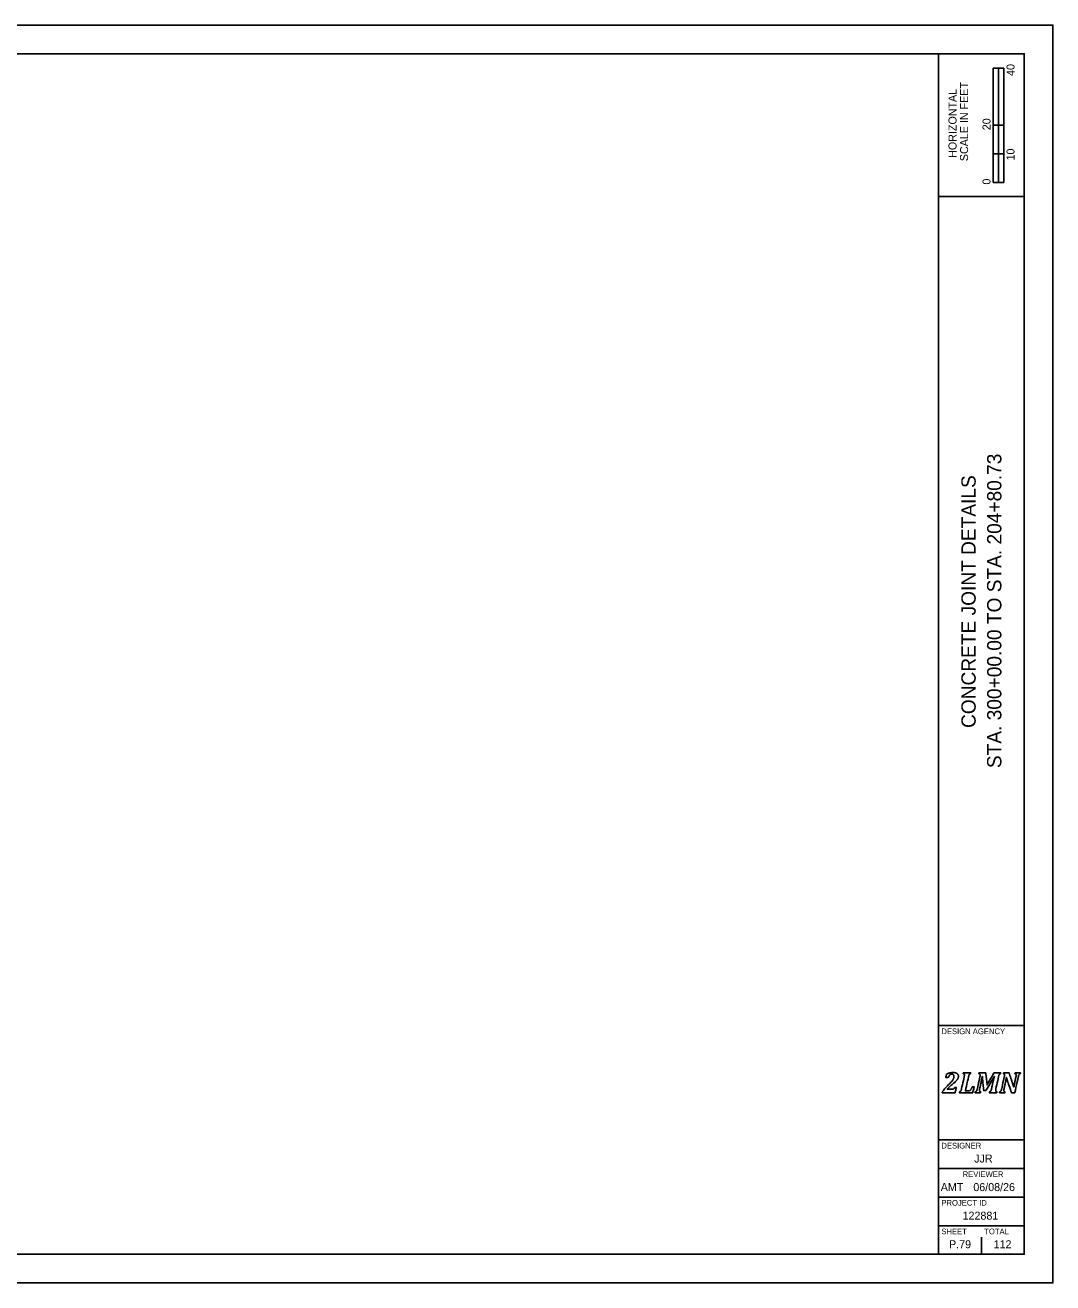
# Model space of a CAD drawing. Extents: x -2 to 34, y 0 to 22.
# Drawn here: x 16.02 to 34, y 0 to 22 of the extents above; entities that cross this region are included whole.
import ezdxf

# ---------------------------------------------------------------- set-up
doc = ezdxf.new("R2010")
doc.units = 0
for name, color, linetype in [('SH_Border', 7, 'Continuous'), ('SH_Cut_Line', 7, 'Continuous'), ('SH_Data', 7, 'Continuous')]:
    doc.layers.add(name, color=color, linetype=linetype)

msp = doc.modelspace()

# ---------------------------------------------------------------- linework, layer by layer
at = {"layer": 'SH_Border'}
for p, q in [((32, 0.5), (32, 21.5)), ((32, 19), (33.5, 19)), ((32, 4.5), (33.5, 4.5)), ((32, 2.5), (33.5, 2.5)), ((32, 2), (33.5, 2)), ((32, 1.5), (33.5, 1.5)), ((32, 1), (33.5, 1))]:
    msp.add_line(p, q, dxfattribs=at)
msp.add_lwpolyline([(1.5, 21.5), (33.5, 21.5), (33.5, 0.5), (1.5, 0.5)], close=True, dxfattribs=at)
at = {"layer": 'SH_Cut_Line'}
msp.add_lwpolyline([(0, 0), (34, 0), (34, 22), (0, 22)], close=True, dxfattribs=at)
at = {"layer": 'SH_Data'}
for p, q in [((32.957, 19.25), (32.957, 21.25)), ((33.144, 21.25), (32.957, 21.25)), ((32.957, 20.25), (32.957, 21.25)), ((32.957, 21.25), (33.05, 21.25)), ((33.05, 21.25), (33.051, 21.25)), ((33.051, 21.25), (33.051, 20.25)), ((33.144, 21.25), (33.144, 19.25)), ((33.051, 20.25), (32.957, 20.25)), ((33.143, 20.25), (33.05, 20.25)), ((33.05, 20.25), (33.05, 19.75)), ((33.143, 19.75), (33.143, 20.25)), ((33.05, 19.75), (32.957, 19.75)), ((32.957, 19.75), (32.957, 19.25)), ((33.05, 19.25), (33.05, 19.75)), ((33.05, 19.75), (33.143, 19.75)), ((33.144, 19.25), (32.957, 19.25)), ((32.957, 19.25), (33.05, 19.25)), ((32.75, 3.5), (32.75, 3.5)), ((32.375, 0.675), (32.375, 0.675)), ((32.75, 0.5), (32.75, 0.8))]:
    msp.add_line(p, q, dxfattribs=at)
for points in [[(32.237, 3.388), (32.246, 3.388), (32.253, 3.389), (32.258, 3.39), (32.263, 3.392), (32.267, 3.394), (32.27, 3.397), (32.273, 3.401), (32.277, 3.408), (32.281, 3.417), (32.281, 3.417), (32.312, 3.417), (32.312, 3.417), (32.312, 3.417), (32.29, 3.326), (32.29, 3.326), (32.29, 3.326), (32.066, 3.326), (32.066, 3.326), (32.066, 3.326), (32.069, 3.343), (32.069, 3.343), (32.078, 3.358), (32.091, 3.375), (32.106, 3.394), (32.122, 3.412), (32.144, 3.435), (32.172, 3.462), (32.197, 3.486), (32.217, 3.506), (32.23, 3.521), (32.243, 3.537), (32.253, 3.551), (32.259, 3.566), (32.266, 3.58), (32.269, 3.595), (32.269, 3.61), (32.269, 3.622), (32.266, 3.632), (32.26, 3.64), (32.253, 3.647), (32.245, 3.65), (32.234, 3.65), (32.22, 3.65), (32.208, 3.646), (32.198, 3.636), (32.188, 3.627), (32.18, 3.613), (32.172, 3.593), (32.172, 3.593), (32.126, 3.593), (32.126, 3.593), (32.126, 3.593), (32.14, 3.654), (32.14, 3.654), (32.166, 3.663), (32.188, 3.669), (32.205, 3.673), (32.223, 3.676), (32.24, 3.678), (32.258, 3.678), (32.278, 3.678), (32.295, 3.675), (32.309, 3.669), (32.322, 3.664), (32.332, 3.656), (32.339, 3.646), (32.345, 3.637), (32.348, 3.626), (32.348, 3.613), (32.348, 3.602), (32.346, 3.591), (32.342, 3.581), (32.339, 3.571), (32.333, 3.56), (32.324, 3.549), (32.315, 3.539), (32.304, 3.526), (32.289, 3.513), (32.275, 3.499), (32.254, 3.482), (32.228, 3.46), (32.216, 3.45), (32.202, 3.438), (32.188, 3.425), (32.174, 3.412), (32.162, 3.4), (32.154, 3.391), (32.154, 3.391), (32.153, 3.388), (32.153, 3.388), (32.153, 3.388), (32.237, 3.388), (32.237, 3.388)], [(32.237, 3.388), (32.237, 3.388), (32.153, 3.388), (32.153, 3.388), (32.153, 3.388), (32.154, 3.391), (32.154, 3.391), (32.162, 3.4), (32.174, 3.412), (32.188, 3.425), (32.202, 3.438), (32.216, 3.45), (32.228, 3.46), (32.254, 3.482), (32.275, 3.499), (32.289, 3.513), (32.304, 3.526), (32.315, 3.539), (32.324, 3.549), (32.333, 3.56), (32.339, 3.571), (32.342, 3.581), (32.346, 3.591), (32.348, 3.602), (32.348, 3.613), (32.348, 3.626), (32.345, 3.637), (32.339, 3.646), (32.332, 3.656), (32.322, 3.664), (32.309, 3.669), (32.295, 3.675), (32.278, 3.678), (32.258, 3.678), (32.24, 3.678), (32.223, 3.676), (32.205, 3.673), (32.188, 3.669), (32.166, 3.663), (32.14, 3.654), (32.14, 3.654), (32.126, 3.593), (32.126, 3.593), (32.126, 3.593), (32.172, 3.593), (32.172, 3.593), (32.18, 3.613), (32.188, 3.627), (32.198, 3.636), (32.208, 3.646), (32.22, 3.65), (32.234, 3.65), (32.245, 3.65), (32.253, 3.647), (32.26, 3.64), (32.266, 3.632), (32.269, 3.622), (32.269, 3.61), (32.269, 3.595), (32.266, 3.58), (32.259, 3.566), (32.253, 3.551), (32.243, 3.537), (32.23, 3.521), (32.217, 3.506), (32.197, 3.486), (32.172, 3.462), (32.144, 3.435), (32.122, 3.412), (32.106, 3.394), (32.091, 3.375), (32.078, 3.358), (32.069, 3.343), (32.069, 3.343), (32.066, 3.326), (32.066, 3.326), (32.066, 3.326), (32.29, 3.326), (32.29, 3.326), (32.29, 3.326), (32.312, 3.417), (32.312, 3.417), (32.312, 3.417), (32.281, 3.417), (32.281, 3.417), (32.277, 3.408), (32.273, 3.401), (32.27, 3.397), (32.267, 3.394), (32.263, 3.392), (32.258, 3.39), (32.253, 3.389), (32.246, 3.388), (32.237, 3.388)], [(32.518, 3.356), (32.527, 3.356), (32.533, 3.357), (32.538, 3.358), (32.542, 3.36), (32.546, 3.362), (32.55, 3.365), (32.554, 3.368), (32.558, 3.372), (32.562, 3.377), (32.567, 3.382), (32.571, 3.388), (32.576, 3.397), (32.58, 3.405), (32.585, 3.415), (32.589, 3.427), (32.589, 3.427), (32.624, 3.427), (32.624, 3.427), (32.624, 3.427), (32.598, 3.326), (32.598, 3.326), (32.598, 3.326), (32.365, 3.326), (32.365, 3.326), (32.365, 3.326), (32.369, 3.343), (32.369, 3.343), (32.376, 3.345), (32.381, 3.348), (32.385, 3.351), (32.389, 3.355), (32.392, 3.36), (32.395, 3.366), (32.398, 3.373), (32.4, 3.382), (32.403, 3.395), (32.403, 3.395), (32.449, 3.605), (32.449, 3.605), (32.452, 3.615), (32.453, 3.625), (32.453, 3.635), (32.453, 3.642), (32.451, 3.647), (32.448, 3.651), (32.444, 3.654), (32.439, 3.656), (32.432, 3.657), (32.432, 3.657), (32.435, 3.674), (32.435, 3.674), (32.435, 3.674), (32.563, 3.674), (32.563, 3.674), (32.563, 3.674), (32.559, 3.657), (32.559, 3.657), (32.552, 3.655), (32.547, 3.652), (32.543, 3.649), (32.539, 3.645), (32.536, 3.64), (32.533, 3.634), (32.531, 3.627), (32.528, 3.618), (32.525, 3.605), (32.525, 3.605), (32.47, 3.356), (32.47, 3.356), (32.47, 3.356), (32.518, 3.356), (32.518, 3.356)], [(32.518, 3.356), (32.518, 3.356), (32.47, 3.356), (32.47, 3.356), (32.47, 3.356), (32.525, 3.605), (32.525, 3.605), (32.528, 3.618), (32.531, 3.627), (32.533, 3.634), (32.536, 3.64), (32.539, 3.645), (32.543, 3.649), (32.547, 3.652), (32.552, 3.655), (32.559, 3.657), (32.559, 3.657), (32.563, 3.674), (32.563, 3.674), (32.563, 3.674), (32.435, 3.674), (32.435, 3.674), (32.435, 3.674), (32.432, 3.657), (32.432, 3.657), (32.439, 3.656), (32.444, 3.654), (32.448, 3.651), (32.451, 3.647), (32.453, 3.642), (32.453, 3.635), (32.453, 3.625), (32.452, 3.615), (32.449, 3.605), (32.449, 3.605), (32.403, 3.395), (32.403, 3.395), (32.4, 3.382), (32.398, 3.373), (32.395, 3.366), (32.392, 3.36), (32.389, 3.355), (32.385, 3.351), (32.381, 3.348), (32.376, 3.345), (32.369, 3.343), (32.369, 3.343), (32.365, 3.326), (32.365, 3.326), (32.365, 3.326), (32.598, 3.326), (32.598, 3.326), (32.598, 3.326), (32.624, 3.427), (32.624, 3.427), (32.624, 3.427), (32.589, 3.427), (32.589, 3.427), (32.585, 3.415), (32.58, 3.405), (32.576, 3.397), (32.571, 3.388), (32.567, 3.382), (32.562, 3.377), (32.558, 3.372), (32.554, 3.368), (32.55, 3.365), (32.546, 3.362), (32.542, 3.36), (32.538, 3.358), (32.533, 3.357), (32.527, 3.356), (32.518, 3.356)], [(32.829, 3.674), (32.829, 3.674), (32.849, 3.461), (32.849, 3.461), (32.849, 3.461), (32.969, 3.674), (32.969, 3.674), (32.969, 3.674), (33.087, 3.674), (33.087, 3.674), (33.087, 3.674), (33.084, 3.657), (33.084, 3.657), (33.077, 3.655), (33.071, 3.652), (33.067, 3.649), (33.064, 3.645), (33.06, 3.64), (33.058, 3.634), (33.055, 3.627), (33.052, 3.618), (33.05, 3.605), (33.05, 3.605), (33.003, 3.395), (33.003, 3.395), (33.002, 3.39), (33.002, 3.387), (33.001, 3.384), (33.001, 3.382), (33.001, 3.379), (33, 3.376), (33, 3.373), (33, 3.369), (33, 3.365), (33, 3.358), (33.002, 3.353), (33.005, 3.349), (33.008, 3.346), (33.014, 3.344), (33.021, 3.343), (33.021, 3.343), (33.018, 3.326), (33.018, 3.326), (33.018, 3.326), (32.89, 3.326), (32.89, 3.326), (32.89, 3.326), (32.893, 3.343), (32.893, 3.343), (32.9, 3.345), (32.906, 3.348), (32.91, 3.351), (32.914, 3.355), (32.917, 3.36), (32.919, 3.366), (32.922, 3.373), (32.925, 3.382), (32.928, 3.395), (32.928, 3.395), (32.951, 3.502), (32.951, 3.502), (32.954, 3.513), (32.957, 3.529), (32.962, 3.548), (32.967, 3.568), (32.972, 3.588), (32.978, 3.609), (32.978, 3.609), (32.973, 3.609), (32.973, 3.609), (32.965, 3.594), (32.957, 3.579), (32.948, 3.563), (32.948, 3.563), (32.833, 3.364), (32.833, 3.364), (32.833, 3.364), (32.792, 3.364), (32.792, 3.364), (32.792, 3.364), (32.775, 3.518), (32.775, 3.518), (32.773, 3.537), (32.772, 3.554), (32.77, 3.569), (32.769, 3.583), (32.768, 3.597), (32.768, 3.611), (32.768, 3.611), (32.764, 3.611), (32.764, 3.611), (32.761, 3.596), (32.758, 3.578), (32.755, 3.558), (32.751, 3.538), (32.747, 3.521), (32.744, 3.507), (32.744, 3.507), (32.72, 3.395), (32.72, 3.395), (32.719, 3.39), (32.718, 3.387), (32.718, 3.384), (32.717, 3.382), (32.717, 3.379), (32.717, 3.376), (32.717, 3.373), (32.716, 3.369), (32.716, 3.365), (32.716, 3.358), (32.718, 3.353), (32.721, 3.349), (32.725, 3.346), (32.73, 3.344), (32.738, 3.343), (32.738, 3.343), (32.734, 3.326), (32.734, 3.326), (32.734, 3.326), (32.641, 3.326), (32.641, 3.326), (32.641, 3.326), (32.644, 3.343), (32.644, 3.343), (32.651, 3.345), (32.657, 3.348), (32.661, 3.351), (32.665, 3.355), (32.668, 3.36), (32.67, 3.366), (32.673, 3.373), (32.676, 3.382), (32.679, 3.395), (32.679, 3.395), (32.725, 3.605), (32.725, 3.605), (32.727, 3.615), (32.728, 3.625), (32.728, 3.635), (32.728, 3.642), (32.727, 3.647), (32.723, 3.651), (32.72, 3.654), (32.715, 3.656), (32.707, 3.657), (32.707, 3.657), (32.711, 3.674), (32.711, 3.674), (32.711, 3.674), (32.829, 3.674), (32.829, 3.674)], [(32.829, 3.674), (32.829, 3.674), (32.711, 3.674), (32.711, 3.674), (32.711, 3.674), (32.707, 3.657), (32.707, 3.657), (32.715, 3.656), (32.72, 3.654), (32.723, 3.651), (32.727, 3.647), (32.728, 3.642), (32.728, 3.635), (32.728, 3.625), (32.727, 3.615), (32.725, 3.605), (32.725, 3.605), (32.679, 3.395), (32.679, 3.395), (32.676, 3.382), (32.673, 3.373), (32.67, 3.366), (32.668, 3.36), (32.665, 3.355), (32.661, 3.351), (32.657, 3.348), (32.651, 3.345), (32.644, 3.343), (32.644, 3.343), (32.641, 3.326), (32.641, 3.326), (32.641, 3.326), (32.734, 3.326), (32.734, 3.326), (32.734, 3.326), (32.738, 3.343), (32.738, 3.343), (32.73, 3.344), (32.725, 3.346), (32.721, 3.349), (32.718, 3.353), (32.716, 3.358), (32.716, 3.365), (32.716, 3.369), (32.717, 3.373), (32.717, 3.376), (32.717, 3.379), (32.717, 3.382), (32.718, 3.384), (32.718, 3.387), (32.719, 3.39), (32.72, 3.395), (32.72, 3.395), (32.744, 3.507), (32.744, 3.507), (32.747, 3.521), (32.751, 3.538), (32.755, 3.558), (32.758, 3.578), (32.761, 3.596), (32.764, 3.611), (32.764, 3.611), (32.768, 3.611), (32.768, 3.611), (32.768, 3.597), (32.769, 3.583), (32.77, 3.569), (32.772, 3.554), (32.773, 3.537), (32.775, 3.518), (32.775, 3.518), (32.792, 3.364), (32.792, 3.364), (32.792, 3.364), (32.833, 3.364), (32.833, 3.364), (32.833, 3.364), (32.948, 3.563), (32.948, 3.563), (32.957, 3.579), (32.965, 3.594), (32.973, 3.609), (32.973, 3.609), (32.978, 3.609), (32.978, 3.609), (32.972, 3.588), (32.967, 3.568), (32.962, 3.548), (32.957, 3.529), (32.954, 3.513), (32.951, 3.502), (32.951, 3.502), (32.928, 3.395), (32.928, 3.395), (32.925, 3.382), (32.922, 3.373), (32.919, 3.366), (32.917, 3.36), (32.914, 3.355), (32.91, 3.351), (32.906, 3.348), (32.9, 3.345), (32.893, 3.343), (32.893, 3.343), (32.89, 3.326), (32.89, 3.326), (32.89, 3.326), (33.018, 3.326), (33.018, 3.326), (33.018, 3.326), (33.021, 3.343), (33.021, 3.343), (33.014, 3.344), (33.008, 3.346), (33.005, 3.349), (33.002, 3.353), (33, 3.358), (33, 3.365), (33, 3.369), (33, 3.373), (33, 3.376), (33.001, 3.379), (33.001, 3.382), (33.001, 3.384), (33.002, 3.387), (33.002, 3.39), (33.003, 3.395), (33.003, 3.395), (33.05, 3.605), (33.05, 3.605), (33.052, 3.618), (33.055, 3.627), (33.058, 3.634), (33.06, 3.64), (33.064, 3.645), (33.067, 3.649), (33.071, 3.652), (33.077, 3.655), (33.084, 3.657), (33.084, 3.657), (33.087, 3.674), (33.087, 3.674), (33.087, 3.674), (32.969, 3.674), (32.969, 3.674), (32.969, 3.674), (32.849, 3.461), (32.849, 3.461), (32.849, 3.461), (32.829, 3.674), (32.829, 3.674)], [(33.137, 3.674), (33.137, 3.674), (33.234, 3.674), (33.234, 3.674), (33.234, 3.674), (33.283, 3.53), (33.283, 3.53), (33.296, 3.49), (33.307, 3.456), (33.315, 3.426), (33.315, 3.426), (33.318, 3.426), (33.318, 3.426), (33.323, 3.455), (33.329, 3.488), (33.337, 3.523), (33.337, 3.523), (33.355, 3.605), (33.355, 3.605), (33.357, 3.615), (33.358, 3.625), (33.358, 3.635), (33.358, 3.642), (33.357, 3.647), (33.353, 3.651), (33.35, 3.654), (33.345, 3.656), (33.337, 3.657), (33.337, 3.657), (33.341, 3.674), (33.341, 3.674), (33.341, 3.674), (33.434, 3.674), (33.434, 3.674), (33.434, 3.674), (33.431, 3.657), (33.431, 3.657), (33.424, 3.655), (33.418, 3.652), (33.414, 3.649), (33.41, 3.645), (33.407, 3.64), (33.405, 3.634), (33.402, 3.627), (33.399, 3.618), (33.396, 3.605), (33.396, 3.605), (33.335, 3.326), (33.335, 3.326), (33.335, 3.326), (33.277, 3.326), (33.277, 3.326), (33.277, 3.326), (33.216, 3.504), (33.216, 3.504), (33.211, 3.518), (33.207, 3.531), (33.204, 3.543), (33.2, 3.556), (33.195, 3.571), (33.19, 3.59), (33.19, 3.59), (33.186, 3.59), (33.186, 3.59), (33.185, 3.579), (33.182, 3.563), (33.179, 3.543), (33.175, 3.523), (33.17, 3.501), (33.165, 3.478), (33.165, 3.478), (33.147, 3.395), (33.147, 3.395), (33.146, 3.39), (33.145, 3.387), (33.145, 3.384), (33.144, 3.382), (33.144, 3.379), (33.144, 3.376), (33.143, 3.373), (33.143, 3.369), (33.143, 3.365), (33.143, 3.358), (33.145, 3.353), (33.148, 3.349), (33.152, 3.346), (33.157, 3.344), (33.164, 3.343), (33.164, 3.343), (33.161, 3.326), (33.161, 3.326), (33.161, 3.326), (33.067, 3.326), (33.067, 3.326), (33.067, 3.326), (33.071, 3.343), (33.071, 3.343), (33.078, 3.345), (33.083, 3.348), (33.087, 3.351), (33.091, 3.355), (33.094, 3.36), (33.097, 3.366), (33.1, 3.373), (33.102, 3.382), (33.105, 3.395), (33.105, 3.395), (33.151, 3.605), (33.151, 3.605), (33.154, 3.615), (33.155, 3.625), (33.155, 3.635), (33.155, 3.642), (33.153, 3.647), (33.15, 3.651), (33.146, 3.654), (33.141, 3.656), (33.134, 3.657), (33.134, 3.657), (33.137, 3.674), (33.137, 3.674)], [(33.137, 3.674), (33.137, 3.674), (33.134, 3.657), (33.134, 3.657), (33.141, 3.656), (33.146, 3.654), (33.15, 3.651), (33.153, 3.647), (33.155, 3.642), (33.155, 3.635), (33.155, 3.625), (33.154, 3.615), (33.151, 3.605), (33.151, 3.605), (33.105, 3.395), (33.105, 3.395), (33.102, 3.382), (33.1, 3.373), (33.097, 3.366), (33.094, 3.36), (33.091, 3.355), (33.087, 3.351), (33.083, 3.348), (33.078, 3.345), (33.071, 3.343), (33.071, 3.343), (33.067, 3.326), (33.067, 3.326), (33.067, 3.326), (33.161, 3.326), (33.161, 3.326), (33.161, 3.326), (33.164, 3.343), (33.164, 3.343), (33.157, 3.344), (33.152, 3.346), (33.148, 3.349), (33.145, 3.353), (33.143, 3.358), (33.143, 3.365), (33.143, 3.369), (33.143, 3.373), (33.144, 3.376), (33.144, 3.379), (33.144, 3.382), (33.145, 3.384), (33.145, 3.387), (33.146, 3.39), (33.147, 3.395), (33.147, 3.395), (33.165, 3.478), (33.165, 3.478), (33.17, 3.501), (33.175, 3.523), (33.179, 3.543), (33.182, 3.563), (33.185, 3.579), (33.186, 3.59), (33.186, 3.59), (33.19, 3.59), (33.19, 3.59), (33.195, 3.571), (33.2, 3.556), (33.204, 3.543), (33.207, 3.531), (33.211, 3.518), (33.216, 3.504), (33.216, 3.504), (33.277, 3.326), (33.277, 3.326), (33.277, 3.326), (33.335, 3.326), (33.335, 3.326), (33.335, 3.326), (33.396, 3.605), (33.396, 3.605), (33.399, 3.618), (33.402, 3.627), (33.405, 3.634), (33.407, 3.64), (33.41, 3.645), (33.414, 3.649), (33.418, 3.652), (33.424, 3.655), (33.431, 3.657), (33.431, 3.657), (33.434, 3.674), (33.434, 3.674), (33.434, 3.674), (33.341, 3.674), (33.341, 3.674), (33.341, 3.674), (33.337, 3.657), (33.337, 3.657), (33.345, 3.656), (33.35, 3.654), (33.353, 3.651), (33.357, 3.647), (33.358, 3.642), (33.358, 3.635), (33.358, 3.625), (33.357, 3.615), (33.355, 3.605), (33.355, 3.605), (33.337, 3.523), (33.337, 3.523), (33.329, 3.488), (33.323, 3.455), (33.318, 3.426), (33.318, 3.426), (33.315, 3.426), (33.315, 3.426), (33.307, 3.456), (33.296, 3.49), (33.283, 3.53), (33.283, 3.53), (33.234, 3.674), (33.234, 3.674), (33.234, 3.674), (33.137, 3.674), (33.137, 3.674)]]:
    msp.add_open_spline(points, degree=3, dxfattribs=at)

# ---------------------------------------------------------------- texts
for s, height, p in [('40', 0.14, (33.33, 21.112)), ('SCALE IN FEET', 0.14, (32.517, 19.621)), ('HORIZONTAL', 0.14, (32.315, 19.679)), ('20', 0.14, (32.91, 20.162)), ('10', 0.14, (33.33, 19.633)), ('0', 0.14, (32.91, 19.211)), ('STA. 300+00.00 TO STA. 204+80.73', 0.25, (33.1, 9.004)), ('CONCRETE JOINT DETAILS', 0.25, (32.65, 9.706))]:
    msp.add_text(s, height=height, rotation=90, dxfattribs=at).set_placement(p)
for s, height, p in [('DESIGN AGENCY', 0.1, (32.05, 4.35)), ('DESIGNER', 0.1, (32.05, 2.35)), ('JJR', 0.14, (32.624, 2.105)), ('REVIEWER', 0.1, (32.422, 1.85)), ('AMT', 0.14, (32.039, 1.605)), ('06/08/26', 0.14, (32.609, 1.605)), ('PROJECT ID', 0.1, (32.05, 1.35)), ('122881', 0.14, (32.421, 1.105)), ('SHEET', 0.1, (32.05, 0.85)), ('TOTAL', 0.1, (32.8, 0.85)), ('P.79', 0.14, (32.184, 0.605)), ('112', 0.14, (32.964, 0.605))]:
    msp.add_text(s, height=height, dxfattribs=at).set_placement(p)

doc.saveas('drawing.dxf')
